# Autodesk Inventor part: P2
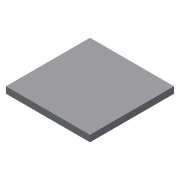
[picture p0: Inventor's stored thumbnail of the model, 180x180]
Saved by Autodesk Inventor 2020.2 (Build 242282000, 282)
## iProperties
Created: 2005-11
Part Number: P2
Document SubType Name: Modeling
Designer: F.Stasiak
Density: 1 g/cm^3
Material: Ogólny
Appearance: Domyślna
Manager: www.cadconsulting.pl
Company: Fabian Stasiak CAD Consulting
Author: F.Stasiak
Subject: Zbiór ćwiczeń. Autodesk Inventor 2020. Kurs podstawowy
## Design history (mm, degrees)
sketch "Szkic1"
  geometry: L1 (65, 65)-(65, -65); L2 (65, -65)-(-65, -65); L3 (-65, -65)-(-65, 65); L4 (-65, 65)-(65, 65); 2 further points
  constraints: 8 end point, 1 coincident, 7 other
  dimensions: "d0" = 130 distance of L1.end L2.end
extrude "Wyciągnięcie proste1" new body sketch "Szkic1" distance "d1" = 10; taper "d2" = 0 deg
node "Bryła1"
node "Korpusy bryłowe"
node "Korpusy powierzchniowe"
